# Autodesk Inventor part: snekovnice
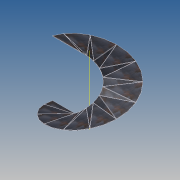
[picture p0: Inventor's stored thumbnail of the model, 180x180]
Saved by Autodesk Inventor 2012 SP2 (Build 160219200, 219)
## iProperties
Created: 2013-06
Part Number: snekovnice
Cost Center: 0 kg
Material: Ocel
Description: =<title> <subject>
Document SubType Name: Plech
Designer: ZACEK
Authority: 0 mm^3
Density: 7.85 g/cm^3
Sheet Metal Rule: Výchozí_mm
Sheet Metal Width: 450,079 mm
Sheet Metal Length: 446,336 mm
Sheet Metal Area: 200886,178 mm^2
Mass: 2005.97 g
Surface Area: 2600.59 cm^2
Volume: 255.537 cm^3
Flat Pattern Width: 45.0079 cm
Flat Pattern Length: 44.6336 cm
Flat Pattern Area: 2008.86 cm^2
SaveDate: 2011-01-27
SaveTime: 09:50
FileName: PATENT_2010
TotalMass: 0 kg
TotalVolume: 0 mm^3
Mass: 2 kg
Author: ZACEK
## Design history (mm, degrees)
sketch "Náčrt1"
  geometry: L1 (-50, 0)-(-200, 0); 1 further point
  constraints: 2 end point, 1 horizontal
  dimensions: "d0" = 50 distance of L1.start point (0, 0) (= d); "d1" = 200 distance of L1.end point (0, 0) (= D)
feature "Spirála1" sketch "Náčrt1" dims "d2" = 300 (= Stoupání), "d3" = 10, "d4" = 10, "d5" = 0, "d6" = 90 deg, "d7" = 90 deg, "d8" = 0, "d9" = 0
sketch "Náčrt2"
  geometry: L1 (-48.296, -12.941)-(-193.185, -51.764); L2 (-231.822, 0)-(38.637, 0) reference; 1 further point
  constraints: 2 end point, 1 point on line
  dimensions: "d11" = 15 deg angle of L1 L2; "d12" = 50 distance of L1.start point (0, 0) (= d0); "d13" = 200 distance of L1.end point (0, 0) (= d1)
feature "VysunutíDoPlochy1" sketch "Náčrt2" dims "d14" = 300 (= d2), "d15" = 0
feature "Rozdělit1"
feature "Rozdělit2"
feature "Rozdělit3"
feature "Rozdělit4"
feature "Rozdělit5"
feature "Rozdělit6"
feature "Rozdělit7"
feature "Rozdělit8"
feature "Rozdělit9"
feature "Rozdělit10"
feature "Rozdělit11"
feature "Rozdělit12"
feature "Rozdělit13"
feature "Rozdělit14"
feature "Rozdělit15"
feature "Rozdělit16"
feature "Rozdělit17"
feature "Rozdělit18"
feature "Rozdělit19"
feature "Rozdělit20"
feature "Rozdělit21"
feature "Rozdělit22"
feature "Rozdělit23"
sketch "3D náčrt2"
feature "Hraniční záplata25" dims "d244" = 0
feature "Hraniční záplata26" dims "d245" = 0
feature "Hraniční záplata27" dims "d246" = 0
feature "Hraniční záplata28" dims "d247" = 0
feature "Hraniční záplata29" dims "d248" = 0
feature "Hraniční záplata30" dims "d249" = 0
feature "Hraniční záplata31" dims "d250" = 0
feature "Hraniční záplata32" dims "d251" = 0
feature "Hraniční záplata33" dims "d252" = 0
feature "Hraniční záplata34" dims "d253" = 0
feature "Hraniční záplata35" dims "d254" = 0
feature "Hraniční záplata36" dims "d255" = 0
feature "Hraniční záplata37" dims "d256" = 0
feature "Hraniční záplata38" dims "d257" = 0
feature "Hraniční záplata39" dims "d258" = 0
feature "Hraniční záplata40" dims "d259" = 0
feature "Hraniční záplata41" dims "d260" = 0
feature "Hraniční záplata42" dims "d261" = 0
feature "Hraniční záplata43" dims "d262" = 0
feature "Hraniční záplata44" dims "d263" = 0
feature "Hraniční záplata45" dims "d264" = 0
feature "Hraniční záplata46" dims "d265" = 0
feature "Hraniční záplata47" dims "d266" = 0
feature "Hraniční záplata48" dims "d267" = 0
feature "Hraniční záplata49" dims "d268" = 0
sketch "Náčrt23"
  geometry: L1 (150, 0)-(0, 0) reference; L2 (0, 0)-(6.815, -53.252) reference; L3 (150, 0)-(6.815, -53.252) reference; 1 further point
sketch "Náčrt24"
  geometry: L1 (152.767, 0)-(0, 0) reference; L2 (0, 0)-(148.529, -35.734) reference; L3 (148.956, -17.666)-(148.529, -35.734) reference; L4 (152.767, 0)-(148.956, -17.666) reference; 1 further point
sketch "Náčrt25"
  geometry: L1 (152.767, 0)-(0, 0) reference; L2 (152.767, 0)-(140.592, -52.287) reference; L3 (140.592, -52.287)-(115.642, -99.823) reference; L4 (0, 0)-(115.642, -99.823) reference; 1 further point
sketch "Náčrt26"
  geometry: L1 (0, 152.767)-(0, 0) reference; L2 (0, 0)-(35.734, 148.529) reference; L3 (17.666, 148.956)-(35.734, 148.529) reference; L4 (0, 152.767)-(17.666, 148.956) reference; 1 further point
sketch "Náčrt27"
  geometry: L1 (152.767, 0)-(0, 0) reference; L2 (0, 0)-(115.642, -99.823) reference; L3 (140.592, -52.287)-(115.642, -99.823) reference; L4 (152.767, 0)-(140.592, -52.287) reference; 1 further point
sketch "Náčrt28"
  geometry: L1 (0, 152.767)-(0, 0) reference; L2 (0, 0)-(35.734, 148.529) reference; L3 (17.666, 148.956)-(35.734, 148.529) reference; L4 (0, 152.767)-(17.666, 148.956) reference; 1 further point
sketch "Náčrt29"
  geometry: L1 (0, 0)-(0, 152.767) reference; L2 (0, 152.767)-(-99.823, 37.125) reference; L3 (-52.287, 12.175)-(-99.823, 37.125) reference; L4 (0, 0)-(-52.287, 12.175) reference; 1 further point
sketch "Náčrt30"
  geometry: L1 (0, 152.767)-(0, 0) reference; L2 (0, 0)-(35.734, 148.529) reference; L3 (17.666, 148.956)-(35.734, 148.529) reference; L4 (0, 152.767)-(17.666, 148.956) reference; 1 further point
sketch "Náčrt31"
  geometry: L1 (0, 0)-(0, 152.767) reference; L2 (0, 152.767)-(-99.823, 37.125) reference; L3 (-52.287, 12.175)-(-99.823, 37.125) reference; L4 (0, 0)-(-52.287, 12.175) reference; 1 further point
sketch "Náčrt32"
  geometry: L1 (0, 0)-(152.767, 0) reference; L2 (152.767, 0)-(4.238, 35.734) reference; L3 (3.811, 17.666)-(4.238, 35.734) reference; L4 (0, 0)-(3.811, 17.666) reference; 1 further point
sketch "Náčrt33"
  geometry: L1 (0, 0)-(0, 152.767) reference; L2 (0, 152.767)-(-99.823, 37.125) reference; L3 (-52.287, 12.175)-(-99.823, 37.125) reference; L4 (0, 0)-(-52.287, 12.175) reference; 1 further point
sketch "Náčrt34"
  geometry: L1 (152.767, 0)-(4.238, 35.734) reference; L2 (0, 0)-(152.767, 0) reference; L3 (0, 0)-(3.811, 17.666) reference; L4 (3.811, 17.666)-(4.238, 35.734) reference; 1 further point
sketch "Náčrt35"
  geometry: L1 (0, 0)-(152.767, 0) reference; L2 (152.767, 0)-(37.125, 99.823) reference; L3 (12.175, 52.287)-(37.125, 99.823) reference; L4 (0, 0)-(12.175, 52.287) reference; 1 further point
sketch "Náčrt36"
  geometry: L1 (152.767, 0)-(4.238, 35.734) reference; L2 (0, 0)-(152.767, 0) reference; L3 (0, 0)-(3.811, 17.666) reference; L4 (3.811, 17.666)-(4.238, 35.734) reference; 1 further point
sketch "Náčrt37"
  geometry: L1 (152.767, 0)-(37.125, 99.823) reference; L2 (0, 0)-(152.767, 0) reference; L3 (0, 0)-(12.175, 52.287) reference; L4 (12.175, 52.287)-(37.125, 99.823) reference; 1 further point
sketch "Náčrt38"
  geometry: L1 (0, 152.767)-(-35.734, 4.238) reference; L2 (0, 0)-(0, 152.767) reference; L3 (0, 0)-(-17.666, 3.811) reference; L4 (-17.666, 3.811)-(-35.734, 4.238) reference; 1 further point
sketch "Náčrt39"
  geometry: L1 (152.767, 0)-(37.125, 99.823) reference; L2 (0, 0)-(152.767, 0) reference; L3 (0, 0)-(12.175, 52.287) reference; L4 (12.175, 52.287)-(37.125, 99.823) reference; 1 further point
sketch "Náčrt40"
  geometry: L1 (0, 152.767)-(-35.734, 4.238) reference; L2 (0, 0)-(0, 152.767) reference; L3 (0, 0)-(-17.666, 3.811) reference; L4 (-17.666, 3.811)-(-35.734, 4.238) reference; 1 further point
sketch "Náčrt41"
  geometry: L1 (0, 0)-(99.823, 115.642) reference; L2 (52.287, 140.592)-(99.823, 115.642) reference; L3 (0, 152.767)-(0, 0) reference; L4 (0, 152.767)-(52.287, 140.592) reference; 1 further point
sketch "Náčrt42"
  geometry: L1 (0, 0)-(0, 152.767) reference; L2 (0, 152.767)-(-35.734, 4.238) reference; L3 (-17.666, 3.811)-(-35.734, 4.238) reference; L4 (0, 0)-(-17.666, 3.811) reference; 1 further point
sketch "Náčrt43"
  geometry: L1 (0, 0)-(99.823, 115.642) reference; L2 (99.823, 115.642)-(52.287, 140.592) reference; L3 (52.287, 140.592)-(0, 152.767) reference; L4 (0, 152.767)-(0, 0) reference; 1 further point
sketch "Náčrt44"
  geometry: L1 (0, 0)-(148.529, -35.734) reference; L2 (148.956, -17.666)-(148.529, -35.734) reference; L3 (152.767, 0)-(148.956, -17.666) reference; L4 (152.767, 0)-(0, 0) reference; 1 further point
sketch "Náčrt45"
  geometry: L1 (0, 152.767)-(0, 0) reference; L2 (52.287, 140.592)-(0, 152.767) reference; L3 (99.823, 115.642)-(52.287, 140.592) reference; L4 (0, 0)-(99.823, 115.642) reference; 1 further point
sketch "Náčrt46"
  geometry: L1 (152.767, 0)-(0, 0) reference; L2 (0, 0)-(148.529, -35.734) reference; L3 (148.956, -17.666)-(148.529, -35.734) reference; L4 (152.767, 0)-(148.956, -17.666) reference; 1 further point
sketch "Náčrt47"
  geometry: L1 (143.185, 53.252)-(0, 0) reference; L2 (143.185, 53.252)-(150, 0) reference; L3 (0, 0)-(150, 0) reference; 1 further point
node "Plocha34"
node "Plocha35"
node "Plocha36"
node "Plocha37"
node "Plocha38"
node "Plocha39"
node "Plocha40"
node "Plocha41"
node "Plocha42"
node "Plocha43"
node "Plocha44"
node "Plocha45"
node "Plocha46"
node "Plocha47"
node "Plocha48"
node "Plocha49"
node "Plocha50"
node "Plocha51"
node "Plocha52"
node "Plocha53"
node "Plocha54"
node "Plocha55"
node "Plocha56"
node "Plocha57"
node "Plocha58"
node "Těleso8"
node "Objemová tělesa"
node "Povrchová tělesa"
pattern_circular "Kruhové pole1" dims angle "d17" = 360 deg
node "Povrch1"
node "Povrch2"
node "Povrch3"
node "Povrch4"
node "Povrch5"
node "Povrch6"
node "Povrch7"
node "Povrch32"
node "Povrch33"
node "Povrch34"
node "Povrch35"
node "Povrch36"
node "Povrch37"
node "Povrch38"
node "Povrch39"
node "Povrch40"
node "Povrch41"
node "Povrch42"
node "Povrch43"
node "Povrch44"
node "Povrch45"
node "Povrch46"
node "Povrch47"
node "Povrch48"
node "Povrch49"
node "Povrch50"
node "Povrch51"
node "Povrch52"
node "Povrch53"
node "Povrch54"
node "Povrch55"
node "Povrch56"
node "Povrch57"
node "Povrch58"
node "Povrch59"
node "Povrch60"
node "Povrch61"
node "Povrch62"
node "Povrch63"
node "Povrch64"
node "Povrch65"
node "Povrch66"
node "Povrch67"
node "Povrch68"
node "Povrch69"
node "Povrch70"
node "Povrch71"
node "Povrch72"
node "Povrch73"
node "Povrch74"
feature "Deska34" dims "Tloušťka" = 2 (derived)
feature "Deska35" dims "d270" = 2 (= PoloměrOhybu), "d271" = 2 (= ŠířkaVýštipu), "d273" = 4 (= MinimálníZbytek), "Tloušťka" = 2 (derived)
feature "Ohyb30" dims "d270" = 2 (= PoloměrOhybu), "d271" = 2 (= ŠířkaVýštipu), "d272" = 1 (= HloubkaVýštipu), "d273" = 4 (= MinimálníZbytek), "d274" = 2 (= PoloměrOhybu), "Tloušťka" = 2 (derived), "MezeraVystřižení" = 0.01
feature "Deska36" dims "d275" = 2 (= PoloměrOhybu), "d276" = 2 (= ŠířkaVýštipu), "d278" = 4 (= MinimálníZbytek), "Tloušťka" = 2 (derived)
feature "Ohyb31" dims "d275" = 2 (= PoloměrOhybu), "d276" = 2 (= ŠířkaVýštipu), "d277" = 1 (= HloubkaVýštipu), "d278" = 4 (= MinimálníZbytek), "d279" = 2 (= PoloměrOhybu), "Tloušťka" = 2 (derived), "MezeraVystřižení" = 0.01
feature "Deska37" dims "d280" = 2 (= PoloměrOhybu), "d281" = 2 (= ŠířkaVýštipu), "d283" = 4 (= MinimálníZbytek), "Tloušťka" = 2 (derived)
feature "Ohyb32" dims "d280" = 2 (= PoloměrOhybu), "d281" = 2 (= ŠířkaVýštipu), "d282" = 1 (= HloubkaVýštipu), "d283" = 4 (= MinimálníZbytek), "d284" = 2 (= PoloměrOhybu), "Tloušťka" = 2 (derived), "MezeraVystřižení" = 0.01
feature "Deska38" dims "d285" = 2 (= PoloměrOhybu), "d286" = 2 (= ŠířkaVýštipu), "d288" = 4 (= MinimálníZbytek), "Tloušťka" = 2 (derived)
feature "Ohyb33" dims "d285" = 2 (= PoloměrOhybu), "d286" = 2 (= ŠířkaVýštipu), "d287" = 1 (= HloubkaVýštipu), "d288" = 4 (= MinimálníZbytek), "d289" = 2 (= PoloměrOhybu), "Tloušťka" = 2 (derived), "MezeraVystřižení" = 0.01
feature "Deska39" dims "d290" = 2 (= PoloměrOhybu), "d291" = 2 (= ŠířkaVýštipu), "d293" = 4 (= MinimálníZbytek), "Tloušťka" = 2 (derived)
feature "Ohyb34" dims "d290" = 2 (= PoloměrOhybu), "d291" = 2 (= ŠířkaVýštipu), "d292" = 1 (= HloubkaVýštipu), "d293" = 4 (= MinimálníZbytek), "d294" = 2 (= PoloměrOhybu), "Tloušťka" = 2 (derived), "MezeraVystřižení" = 0.01
feature "Deska40" dims "d295" = 2 (= PoloměrOhybu), "d296" = 2 (= ŠířkaVýštipu), "d298" = 4 (= MinimálníZbytek), "Tloušťka" = 2 (derived)
feature "Ohyb35" dims "d295" = 2 (= PoloměrOhybu), "d296" = 2 (= ŠířkaVýštipu), "d297" = 1 (= HloubkaVýštipu), "d298" = 4 (= MinimálníZbytek), "d299" = 2 (= PoloměrOhybu), "Tloušťka" = 2 (derived), "MezeraVystřižení" = 0.01
feature "Deska41" dims "d300" = 2 (= PoloměrOhybu), "d301" = 2 (= ŠířkaVýštipu), "d303" = 4 (= MinimálníZbytek), "Tloušťka" = 2 (derived)
feature "Ohyb36" dims "d300" = 2 (= PoloměrOhybu), "d301" = 2 (= ŠířkaVýštipu), "d302" = 1 (= HloubkaVýštipu), "d303" = 4 (= MinimálníZbytek), "d304" = 2 (= PoloměrOhybu), "Tloušťka" = 2 (derived), "MezeraVystřižení" = 0.01
feature "Deska42" dims "d305" = 2 (= PoloměrOhybu), "d306" = 2 (= ŠířkaVýštipu), "d308" = 4 (= MinimálníZbytek), "Tloušťka" = 2 (derived)
feature "Ohyb37" dims "d305" = 2 (= PoloměrOhybu), "d306" = 2 (= ŠířkaVýštipu), "d307" = 1 (= HloubkaVýštipu), "d308" = 4 (= MinimálníZbytek), "d309" = 2 (= PoloměrOhybu), "Tloušťka" = 2 (derived), "MezeraVystřižení" = 0.01
feature "Deska43" dims "d310" = 2 (= PoloměrOhybu), "d311" = 2 (= ŠířkaVýštipu), "d313" = 4 (= MinimálníZbytek), "Tloušťka" = 2 (derived)
feature "Ohyb38" dims "d310" = 2 (= PoloměrOhybu), "d311" = 2 (= ŠířkaVýštipu), "d312" = 1 (= HloubkaVýštipu), "d313" = 4 (= MinimálníZbytek), "d314" = 2 (= PoloměrOhybu), "Tloušťka" = 2 (derived), "MezeraVystřižení" = 0.01
feature "Deska44" dims "d315" = 2 (= PoloměrOhybu), "d316" = 2 (= ŠířkaVýštipu), "d318" = 4 (= MinimálníZbytek), "Tloušťka" = 2 (derived)
feature "Ohyb39" dims "d315" = 2 (= PoloměrOhybu), "d316" = 2 (= ŠířkaVýštipu), "d317" = 1 (= HloubkaVýštipu), "d318" = 4 (= MinimálníZbytek), "d319" = 2 (= PoloměrOhybu), "Tloušťka" = 2 (derived), "MezeraVystřižení" = 0.01
feature "Deska45" dims "d320" = 2 (= PoloměrOhybu), "d321" = 2 (= ŠířkaVýštipu), "d323" = 4 (= MinimálníZbytek), "Tloušťka" = 2 (derived)
feature "Ohyb40" dims "d320" = 2 (= PoloměrOhybu), "d321" = 2 (= ŠířkaVýštipu), "d322" = 1 (= HloubkaVýštipu), "d323" = 4 (= MinimálníZbytek), "d324" = 2 (= PoloměrOhybu), "Tloušťka" = 2 (derived), "MezeraVystřižení" = 0.01
feature "Deska46" dims "d325" = 2 (= PoloměrOhybu), "d326" = 2 (= ŠířkaVýštipu), "d328" = 4 (= MinimálníZbytek), "Tloušťka" = 2 (derived)
feature "Ohyb41" dims "d325" = 2 (= PoloměrOhybu), "d326" = 2 (= ŠířkaVýštipu), "d327" = 1 (= HloubkaVýštipu), "d328" = 4 (= MinimálníZbytek), "d329" = 2 (= PoloměrOhybu), "Tloušťka" = 2 (derived), "MezeraVystřižení" = 0.01
feature "Deska47" dims "d330" = 2 (= PoloměrOhybu), "d331" = 2 (= ŠířkaVýštipu), "d333" = 4 (= MinimálníZbytek), "Tloušťka" = 2 (derived)
feature "Ohyb42" dims "d330" = 2 (= PoloměrOhybu), "d331" = 2 (= ŠířkaVýštipu), "d332" = 1 (= HloubkaVýštipu), "d333" = 4 (= MinimálníZbytek), "d334" = 2 (= PoloměrOhybu), "Tloušťka" = 2 (derived), "MezeraVystřižení" = 0.01
feature "Deska48" dims "d335" = 2 (= PoloměrOhybu), "d336" = 2 (= ŠířkaVýštipu), "d338" = 4 (= MinimálníZbytek), "Tloušťka" = 2 (derived)
feature "Ohyb43" dims "d335" = 2 (= PoloměrOhybu), "d336" = 2 (= ŠířkaVýštipu), "d337" = 1 (= HloubkaVýštipu), "d338" = 4 (= MinimálníZbytek), "d339" = 2 (= PoloměrOhybu), "Tloušťka" = 2 (derived), "MezeraVystřižení" = 0.01
feature "Deska49" dims "d340" = 2 (= PoloměrOhybu), "d341" = 2 (= ŠířkaVýštipu), "d343" = 4 (= MinimálníZbytek), "Tloušťka" = 2 (derived)
feature "Ohyb44" dims "d340" = 2 (= PoloměrOhybu), "d341" = 2 (= ŠířkaVýštipu), "d342" = 1 (= HloubkaVýštipu), "d343" = 4 (= MinimálníZbytek), "d344" = 2 (= PoloměrOhybu), "Tloušťka" = 2 (derived), "MezeraVystřižení" = 0.01
feature "Deska50" dims "d345" = 2 (= PoloměrOhybu), "d346" = 2 (= ŠířkaVýštipu), "d348" = 4 (= MinimálníZbytek), "Tloušťka" = 2 (derived)
feature "Ohyb45" dims "d345" = 2 (= PoloměrOhybu), "d346" = 2 (= ŠířkaVýštipu), "d347" = 1 (= HloubkaVýštipu), "d348" = 4 (= MinimálníZbytek), "d349" = 2 (= PoloměrOhybu), "Tloušťka" = 2 (derived), "MezeraVystřižení" = 0.01
feature "Deska51" dims "d350" = 2 (= PoloměrOhybu), "d351" = 2 (= ŠířkaVýštipu), "d353" = 4 (= MinimálníZbytek), "Tloušťka" = 2 (derived)
feature "Ohyb46" dims "d350" = 2 (= PoloměrOhybu), "d351" = 2 (= ŠířkaVýštipu), "d352" = 1 (= HloubkaVýštipu), "d353" = 4 (= MinimálníZbytek), "d354" = 2 (= PoloměrOhybu), "Tloušťka" = 2 (derived), "MezeraVystřižení" = 0.01
feature "Deska52" dims "d355" = 2 (= PoloměrOhybu), "d356" = 2 (= ŠířkaVýštipu), "d358" = 4 (= MinimálníZbytek), "Tloušťka" = 2 (derived)
feature "Ohyb47" dims "d355" = 2 (= PoloměrOhybu), "d356" = 2 (= ŠířkaVýštipu), "d357" = 1 (= HloubkaVýštipu), "d358" = 4 (= MinimálníZbytek), "d359" = 2 (= PoloměrOhybu), "Tloušťka" = 2 (derived), "MezeraVystřižení" = 0.01
feature "Deska53" dims "d360" = 2 (= PoloměrOhybu), "d361" = 2 (= ŠířkaVýštipu), "d363" = 4 (= MinimálníZbytek), "Tloušťka" = 2 (derived)
feature "Ohyb48" dims "d360" = 2 (= PoloměrOhybu), "d361" = 2 (= ŠířkaVýštipu), "d362" = 1 (= HloubkaVýštipu), "d363" = 4 (= MinimálníZbytek), "d364" = 2 (= PoloměrOhybu), "Tloušťka" = 2 (derived), "MezeraVystřižení" = 0.01
feature "Deska54" dims "d365" = 2 (= PoloměrOhybu), "d366" = 2 (= ŠířkaVýštipu), "d368" = 4 (= MinimálníZbytek), "Tloušťka" = 2 (derived)
feature "Ohyb49" dims "d365" = 2 (= PoloměrOhybu), "d366" = 2 (= ŠířkaVýštipu), "d367" = 1 (= HloubkaVýštipu), "d368" = 4 (= MinimálníZbytek), "d369" = 2 (= PoloměrOhybu), "Tloušťka" = 2 (derived), "MezeraVystřižení" = 0.01
feature "Deska55" dims "d370" = 2 (= PoloměrOhybu), "d371" = 2 (= ŠířkaVýštipu), "d373" = 4 (= MinimálníZbytek), "Tloušťka" = 2 (derived)
feature "Ohyb50" dims "d370" = 2 (= PoloměrOhybu), "d371" = 2 (= ŠířkaVýštipu), "d372" = 1 (= HloubkaVýštipu), "d373" = 4 (= MinimálníZbytek), "d374" = 2 (= PoloměrOhybu), "Tloušťka" = 2 (derived), "MezeraVystřižení" = 0.01
feature "Deska56" dims "d375" = 2 (= PoloměrOhybu), "d376" = 2 (= ŠířkaVýštipu), "d378" = 4 (= MinimálníZbytek), "Tloušťka" = 2 (derived)
feature "Ohyb51" dims "d375" = 2 (= PoloměrOhybu), "d376" = 2 (= ŠířkaVýštipu), "d377" = 1 (= HloubkaVýštipu), "d378" = 4 (= MinimálníZbytek), "d379" = 2 (= PoloměrOhybu), "Tloušťka" = 2 (derived), "MezeraVystřižení" = 0.01
feature "Deska57" dims "d380" = 2 (= PoloměrOhybu), "d381" = 2 (= ŠířkaVýštipu), "d383" = 4 (= MinimálníZbytek), "Tloušťka" = 2 (derived)
feature "Ohyb52" dims "d380" = 2 (= PoloměrOhybu), "d381" = 2 (= ŠířkaVýštipu), "d382" = 1 (= HloubkaVýštipu), "d383" = 4 (= MinimálníZbytek), "d384" = 2 (= PoloměrOhybu), "Tloušťka" = 2 (derived), "MezeraVystřižení" = 0.01
feature "Deska58" dims "d385" = 2 (= PoloměrOhybu), "d386" = 2 (= ŠířkaVýštipu), "d388" = 4 (= MinimálníZbytek), "Tloušťka" = 2 (derived)
feature "Ohyb53" dims "d385" = 2 (= PoloměrOhybu), "d386" = 2 (= ŠířkaVýštipu), "d387" = 1 (= HloubkaVýštipu), "d388" = 4 (= MinimálníZbytek), "d389" = 2 (= PoloměrOhybu), "Tloušťka" = 2 (derived), "MezeraVystřižení" = 0.01
feature "VysunutíDoPlochy2"
feature "VysunutíDoPlochy3"
feature "VysunutíDoPlochy4"
feature "VysunutíDoPlochy5"
feature "VysunutíDoPlochy6"
feature "VysunutíDoPlochy7"
feature "VysunutíDoPlochy8"
feature "VysunutíDoPlochy9"
feature "VysunutíDoPlochy10"
feature "VysunutíDoPlochy11"
feature "VysunutíDoPlochy12"
feature "VysunutíDoPlochy13"
feature "VysunutíDoPlochy14"
feature "VysunutíDoPlochy15"
feature "VysunutíDoPlochy16"
feature "VysunutíDoPlochy17"
feature "VysunutíDoPlochy18"
feature "VysunutíDoPlochy19"
feature "VysunutíDoPlochy20"
feature "VysunutíDoPlochy21"
feature "VysunutíDoPlochy22"
feature "VysunutíDoPlochy23"
feature "VysunutíDoPlochy24"
feature "Definice1"
other parameters: "KSoučinitel" = 4.4, "PoloměrOhybu" = 2 (= Tloušťka), "ŠířkaVýštipu" = 2 (= Tloušťka), "HloubkaVýštipu" = 1 (= 0.5 x Tloušťka), "VelikostRohovéhoVýštipu" = 8 (= 4 x Tloušťka), "MinimálníZbytek" = 4 (= 2 x Tloušťka), "PřechodovýPoloměr" = 2 (= PoloměrOhybu), "VelikostJacobihoPoloměru" = 2 (= PoloměrOhybu), "VelikostMezery" = 2 (= Tloušťka), "d44" = 2 (= PoloměrOhybu), "d104" = 2 (= PoloměrOhybu), "d123" = 2 (= PoloměrOhybu), "d142" = 2 (= PoloměrOhybu), "d166" = 2 (= PoloměrOhybu), "d208" = 2 (= PoloměrOhybu), "d269" = 2 (= PoloměrOhybu), "d" = 50 [user parameter; used in 1 equation term], "D" = 200 [user parameter; used in 1 equation term], "HloubkaVýštipu" = 1, "MinimálníZbytek" = 4, "PoloměrOhybu" = 2, "PřechodovýPoloměr" = 2, "Tloušťka" = 2, "VelikostJacobihoPoloměru" = 2, "VelikostMezery" = 2, "VelikostRohovéhoVýštipu" = 8, "ŠířkaVýštipu" = 2
